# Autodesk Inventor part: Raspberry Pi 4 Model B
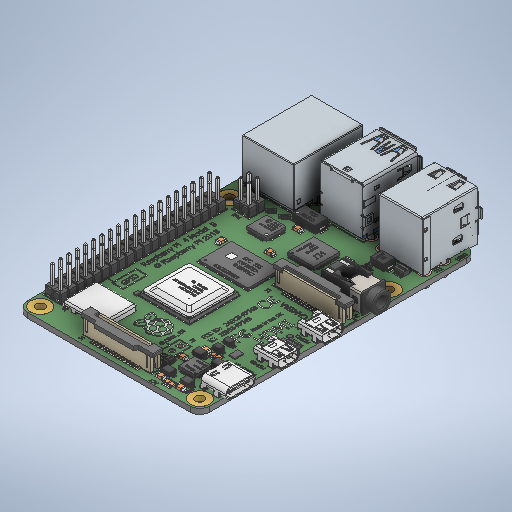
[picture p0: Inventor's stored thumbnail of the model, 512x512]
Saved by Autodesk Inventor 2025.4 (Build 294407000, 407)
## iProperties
Created: 2026-08
Part Number: Raspberry Pi 4 Model B
Material: Generic
Document SubType Name: Modeling
Designer: usuario
Density: 1 g/cm^3
Appearance: Valor por defecto
Title: Raspberry Pi 4 Model B.stp
Author: quang
Sending System: Autodesk Inventor 2024
Preprocessor: ST-DEVELOPER v20
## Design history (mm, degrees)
feature "Solid1"
feature "Solid1:1"
feature "Solid1:2"
feature "Solid1:3"
feature "Solid1:4"
node "Sólido1"
node "Sólido2"
node "Sólido3"
node "Sólido4"
node "Sólido5"
